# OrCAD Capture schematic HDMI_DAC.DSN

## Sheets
1 RGB: size A
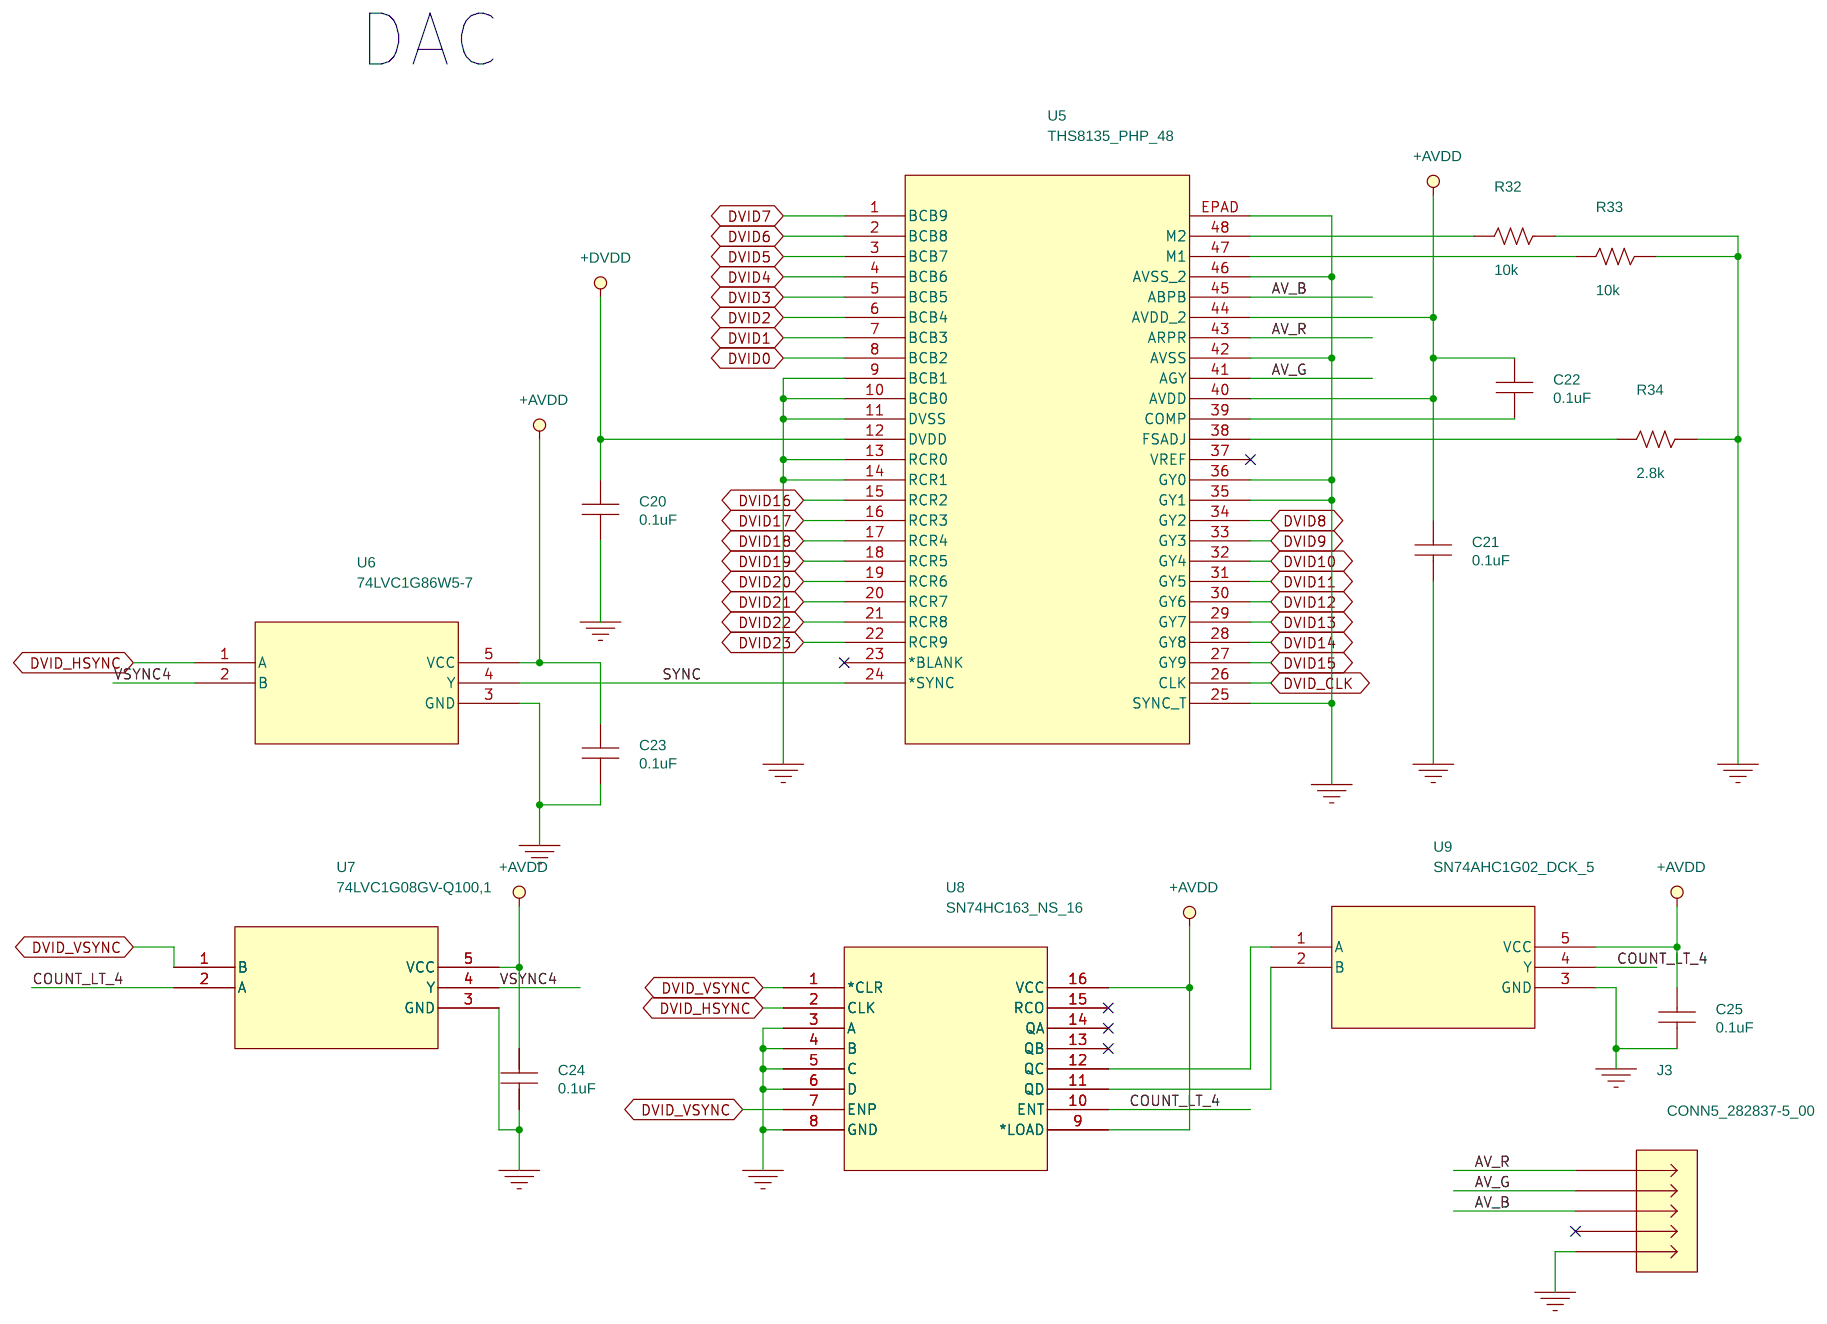
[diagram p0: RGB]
2 HDMI: size A
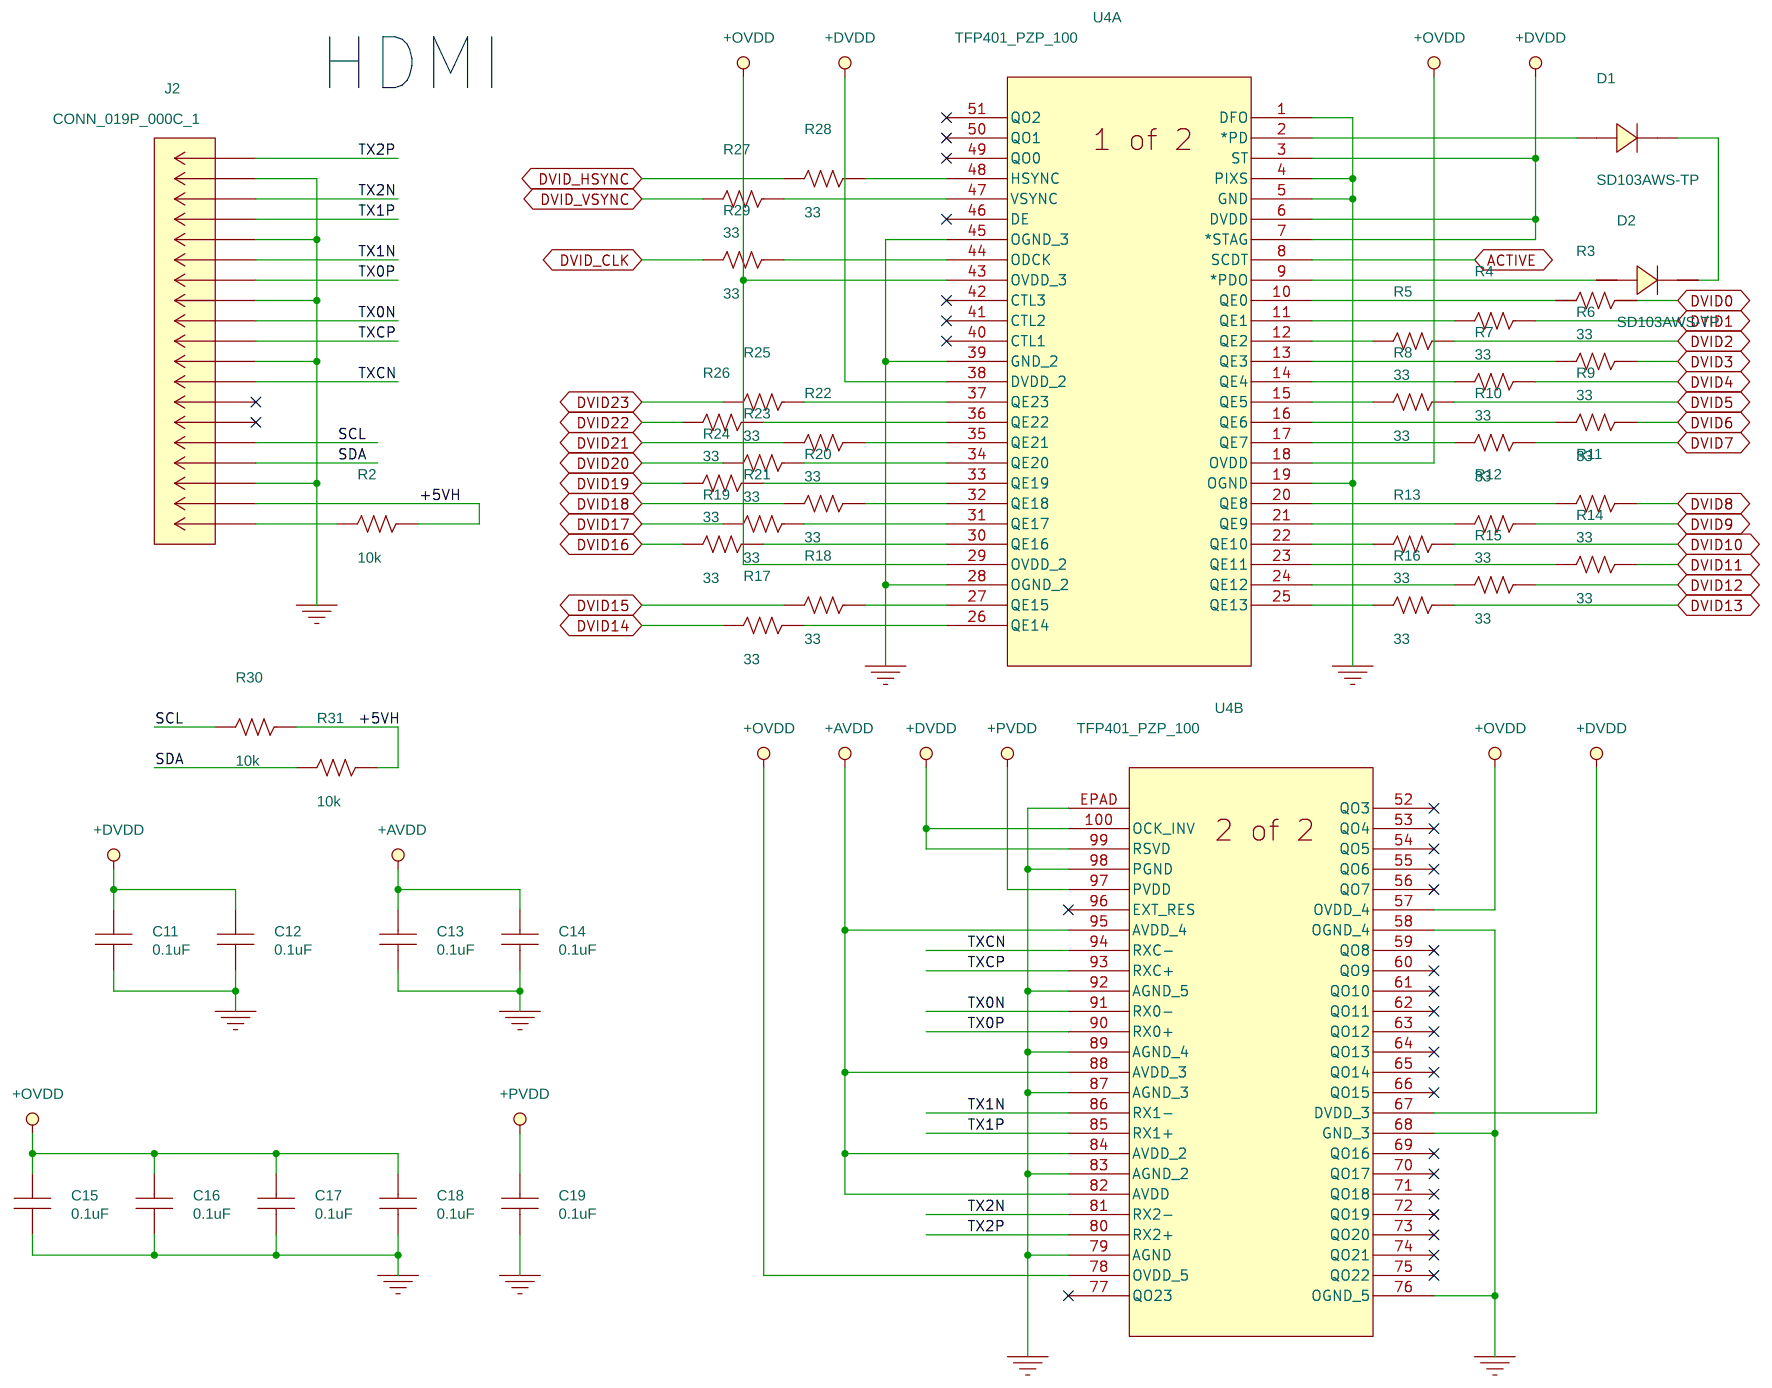
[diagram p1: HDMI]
3 POWER: size A
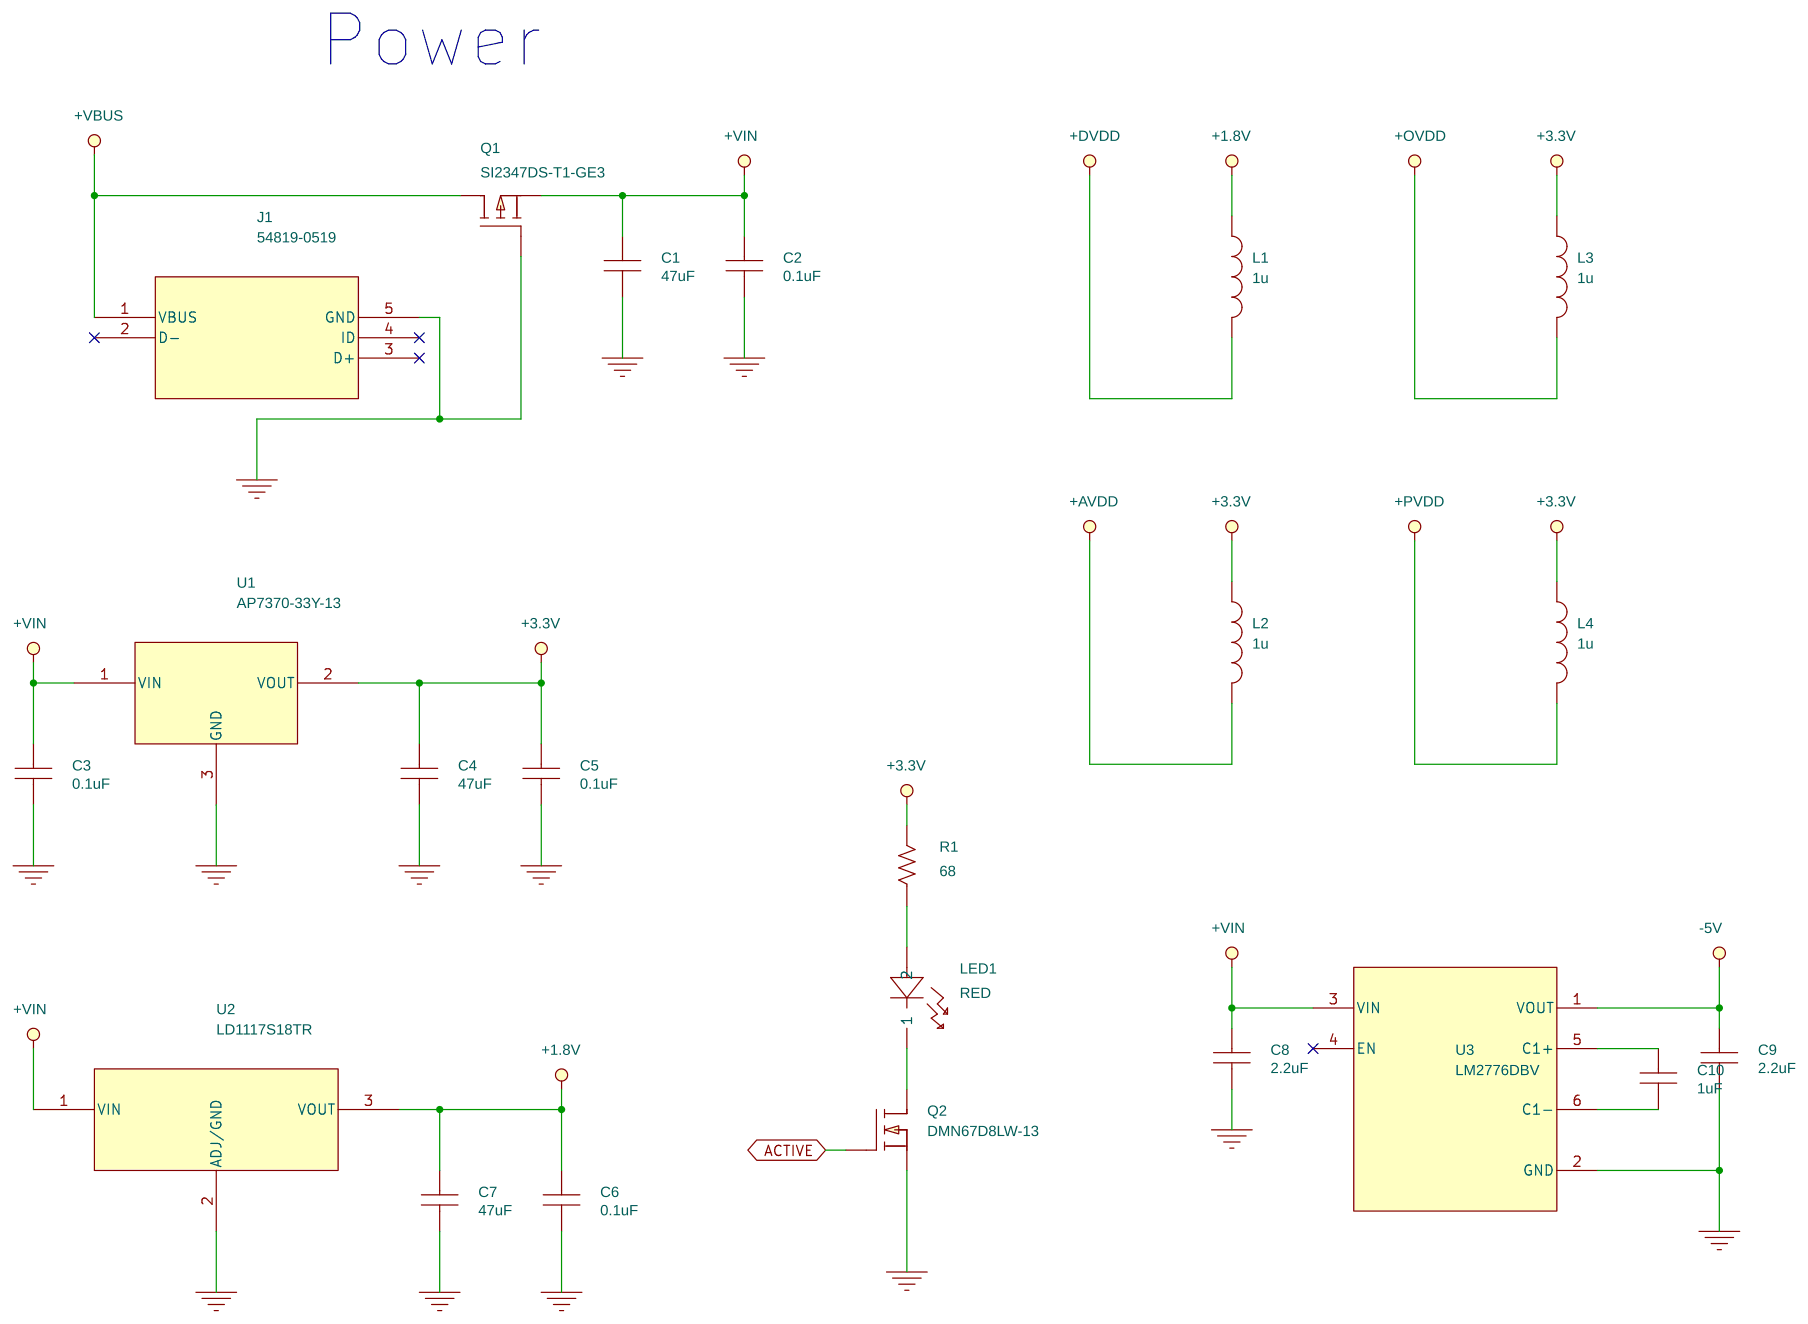
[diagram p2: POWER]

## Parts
sheet HDMI
C11  0.1uF  [SMC0603]
C12  0.1uF  [SMC0603]
C13  0.1uF  [SMC0603]
C14  0.1uF  [SMC0603]
C15  0.1uF  [SMC0603]
C16  0.1uF  [SMC0603]
C17  0.1uF  [SMC0603]
C18  0.1uF  [SMC0603]
C19  0.1uF  [SMC0603]
D1  SD103AWS-TP  [SMD0805]
D2  SD103AWS-TP  [SMD0805]
J2  CONN_019P_000C_1  [CONN_208658-1051_MOL]
R2  10k  [SMR0603]
R3  33  [SMR0603]
R4  33  [SMR0603]
R5  33  [SMR0603]
R6  33  [SMR0603]
R7  33  [SMR0603]
R8  33  [SMR0603]
R9  33  [SMR0603]
R10  33  [SMR0603]
R11  33  [SMR0603]
R12  33  [SMR0603]
R13  33  [SMR0603]
R14  33  [SMR0603]
R15  33  [SMR0603]
R16  33  [SMR0603]
R17  33  [SMR0603]
R18  33  [SMR0603]
R19  33  [SMR0603]
R20  33  [SMR0603]
R21  33  [SMR0603]
R22  33  [SMR0603]
R23  33  [SMR0603]
R24  33  [SMR0603]
R25  33  [SMR0603]
R26  33  [SMR0603]
R27  33  [SMR0603]
R28  33  [SMR0603]
R29  33  [SMR0603]
R30  10k  [SMR0603]
R31  10k  [SMR0603]
U4  TFP401_PZP_100  [PZP100_5P2X5P2]  (sections A,B)
sheet POWER
C1  47uF  [SMC1206]
C2  0.1uF  [SMC0603]
C3  0.1uF  [SMC0603]
C4  47uF  [SMC1206]
C5  0.1uF  [SMC0603]
C6  0.1uF  [SMC0603]
C7  47uF  [SMC1206]
C8  2.2uF  [SMC0603]
C9  2.2uF  [SMC0603]
C10  1uF  [SMC0603]
J1  54819-0519  [54819-0519_MOL]
L1  1u  [SMR0603]
L2  1u  [SMR0603]
L3  1u  [SMR0603]
L4  1u  [SMR0603]
LED1  RED  [LED_LTL-307E_LTO]
Q1  SI2347DS-T1-GE3  [SOT23]
Q2  DMN67D8LW-13  [SOT23]
R1  68  [SMR0603]
U1  AP7370-33Y-13  [SOT89]
U2  LD1117S18TR  [SOT89]
U3  LM2776DBV  [DBV0006A_N]
sheet RGB
C20  0.1uF  [SMC0603]
C21  0.1uF  [SMC0603]
C22  0.1uF  [SMC0603]
C23  0.1uF  [SMC0603]
C24  0.1uF  [SMC0603]
C25  0.1uF  [SMC0603]
J3  CONN5_282837-5_00  [CONN5_282837-5_TEC]
R32  10k  [SMR0603]
R33  10k  [SMR0603]
R34  2.8k  [SMR0603]
U5  THS8135_PHP_48  [PHP48_4P1X4P1]
U6  74LVC1G86W5-7  [SOT25_DIO]
U7  74LVC1G08GV-Q100,1  [SC-74A_SOT753_NEX]
U8  SN74HC163_NS_16  [NS16]
U9  SN74AHC1G02_DCK_5  [DCK5]

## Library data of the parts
C1-C25 = CAP_NP
D1 D2 = DIODE_0
J2 = 2086581051
R1-R34 = R
U4 = TFP401PZP
J1 = 548190519
L1-L4 = INDUCTOR
LED1 = LTL-307E_0
Q1 = MOSFET_EP_GSD
Q2 = MOSFET_EN_GSD
U1 = AP7370-33Y-13_2
U2 = LD1117S18TR_2
U3 = LM2776DBVT
J3 = 282837-5
U5 = THS8135PHP
U6 = 74LVC1G86W5-7
U7 = 74LVC1G08GV-Q100,1
U8 = SN74HC163NSR
U9 = SN74AHC1G02DCKRG4

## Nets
+1.8V: C6.1 C7.1 L1.1 U2.3(VOUT)
+3.3V: C4.1 C5.1 L2.1 L3.1 L4.1 R1.2 U1.2(VOUT)
+5VH: J2.18 R2.1 R30.1 R31.1
+AVDD: C13.1 C14.1 C21.1 C22.1 C23.1 C24.1 C25.1 L2.2 U4.82(AVDD) U4.84(AVDD_2) U4.88(AVDD_3) U4.95(AVDD_4) U5.40(AVDD) U5.44(AVDD_2) U6.5(VCC) U7.5(VCC) U8.9(*LOAD) U8.16(VCC) U9.5(VCC)
+DVDD: C11.1 C12.1 C20.1 L1.2 U4.3(ST) U4.6(DVDD) U4.7(*STAG) U4.38(DVDD_2) U4.67(DVDD_3) U4.99(RSVD) U4.100(OCK_INV) U5.12(DVDD)
+PVDD: C19.1 L4.2 U4.97(PVDD)
+VBUS: J1.1(VBUS) Q1.3(D)
+VIN: C1.1 C2.1 C3.1 C8.1 Q1.2(S) U1.1(VIN) U2.1(VIN) U3.3(VIN)
-5V: C9.1 U3.1(VOUT)
0: C1.2 C2.2 C3.2 C4.2 C5.2 C6.2 C7.2 C8.2 C9.2 C11.2 C12.2 C13.2 C14.2 C15.2 C16.2 C17.2 C18.2 C19.2 C20.2 C21.2 C23.2 C24.2 C25.2 J1.5(GND) J2.2 J2.5 J2.8 J2.11 J2.17 J3.5 Q1.1(G) Q2.2(S) R32.1 R33.1 R34.1 U1.3(GND) U2.2(ADJ/GND) U3.2(GND) U4.1(DFO) U4.4(PIXS) U4.5(GND) U4.19(OGND) U4.28(OGND_2) U4.39(GND_2) U4.45(OGND_3) U4.58(OGND_4) U4.68(GND_3) U4.76(OGND_5) U4.79(AGND) U4.83(AGND_2) U4.87(AGND_3) U4.89(AGND_4) U4.92(AGND_5) U4.98(PGND) U4.EPAD U5.9(BCB1) U5.10(BCB0) U5.11(DVSS) U5.13(RCR0) U5.14(RCR1) U5.25(SYNC_T) U5.35(GY1) U5.36(GY0) U5.42(AVSS) U5.46(AVSS_2) U5.EPAD U6.3(GND) U7.3(GND) U8.3(A) U8.4(B) U8.5(C) U8.6(D) U8.8(GND) U9.3(GND)
+OVDD: C15.1 C16.1 C17.1 C18.1 L3.2 U4.18(OVDD) U4.29(OVDD_2) U4.43(OVDD_3) U4.57(OVDD_4) U4.78(OVDD_5)
ACTIVE: Q2.1(G) U4.8(SCDT)
AV_B: J3.3 U5.45(ABPB)
AV_G: J3.2 U5.41(AGY)
AV_R: J3.1 U5.43(ARPR)
COUNT_LT_4: U7.2(A) U8.10(ENT) U9.4(Y)
DVID0: R3.1 U5.8(BCB2)
DVID1: R4.1 U5.7(BCB3)
DVID2: R5.1 U5.6(BCB4)
DVID3: R6.1 U5.5(BCB5)
DVID4: R7.1 U5.4(BCB6)
DVID5: R8.1 U5.3(BCB7)
DVID6: R9.1 U5.2(BCB8)
DVID7: R10.1 U5.1(BCB9)
DVID8: R11.1 U5.34(GY2)
DVID9: R12.1 U5.33(GY3)
DVID10: R13.1 U5.32(GY4)
DVID11: R14.1 U5.31(GY5)
DVID12: R15.1 U5.30(GY6)
DVID13: R16.1 U5.29(GY7)
DVID14: R17.2 U5.28(GY8)
DVID15: R18.2 U5.27(GY9)
DVID16: R19.2 U5.15(RCR2)
DVID17: R21.2 U5.16(RCR3)
DVID18: R20.2 U5.17(RCR4)
DVID19: R24.2 U5.18(RCR5)
DVID20: R23.2 U5.19(RCR6)
DVID21: R22.2 U5.20(RCR7)
DVID22: R26.2 U5.21(RCR8)
DVID23: R25.2 U5.22(RCR9)
DVID_CLK: R29.2 U5.26(CLK)
DVID_HSYNC: R28.2 U6.1(A) U8.2(CLK)
DVID_VSYNC: R27.2 U7.1(B) U8.1(*CLR) U8.7(ENP)
SCL: J2.15 R30.2
SDA: J2.16 R31.2
SYNC: U5.24(*SYNC) U6.4(Y)
TX0N: J2.9 U4.91(RX0-)
TX0P: J2.7 U4.90(RX0+)
TX1N: J2.6 U4.86(RX1-)
TX1P: J2.4 U4.85(RX1+)
TX2N: J2.3 U4.81(RX2-)
TX2P: J2.1 U4.80(RX2+)
TXCN: J2.12 U4.94(RXC-)
TXCP: J2.10 U4.93(RXC+)
VSYNC4: U6.2(B) U7.4(Y)
N03253: C10.1 U3.5(C1+)
N03257: C10.2 U3.6(C1-)
N03589: LED1.2(1) Q2.3(D)
N03620: LED1.1(2) R1.1
N04135: J2.19 R2.2
N11616: R3.2 U4.10(QE0)
N11680: R4.2 U4.11(QE1)
N11691: R5.2 U4.12(QE2)
N11721: R6.2 U4.13(QE3)
N11753: R7.2 U4.14(QE4)
N11785: R8.2 U4.15(QE5)
N11817: R9.2 U4.16(QE6)
N11849: R10.2 U4.17(QE7)
N12249: R11.2 U4.20(QE8)
N12281: R12.2 U4.21(QE9)
N12313: R13.2 U4.22(QE10)
N12345: R14.2 U4.23(QE11)
N12377: R15.2 U4.24(QE12)
N12409: R16.2 U4.25(QE13)
N12613: R17.1 U4.26(QE14)
N13128: R18.1 U4.27(QE15)
N13531: R19.1 U4.30(QE16)
N13809: R20.1 U4.32(QE18)
N13817: R21.1 U4.31(QE17)
N13972: R22.1 U4.35(QE21)
N14004: R23.1 U4.34(QE20)
N14012: R24.1 U4.33(QE19)
N14149: R25.1 U4.37(QE23)
N14157: R26.1 U4.36(QE22)
N14872: R27.1 U4.47(VSYNC)
N15122: R28.1 U4.48(HSYNC)
N15187: R29.1 U4.44(ODCK)
N15634: D1.A U4.2(*PD)
N15666: D2.A U4.9(*PDO)
N15670: D1.C(K) D2.C(K)
N21441: R32.2 U5.48(M2)
N21445: R33.2 U5.47(M1)
N21637: C22.2 U5.39(COMP)
N21681: R34.2 U5.38(FSADJ)
N25706: U8.11(QD) U9.2(B)
N25713: U8.12(QC) U9.1(A)

Not connected (* = marked no-connect by the designer): J1 2(D-)* 3(D+)* 4(ID)*; J2 13* 14*; J3 4*; U3 4(EN)*; U4 40(CTL1)* 41(CTL2)* 42(CTL3)* 46(DE)* 49(QO0)* 50(QO1)* 51(QO2)* 52(QO3)* 53(QO4)* 54(QO5)* 55(QO6)* 56(QO7)* 59(QO8)* 60(QO9)* 61(QO10)* 62(QO11)* 63(QO12)* 64(QO13)* 65(QO14)* 66(QO15)* 69(QO16)* 70(QO17)* 71(QO18)* 72(QO19)* 73(QO20)* 74(QO21)* 75(QO22)* 77(QO23)* 96(EXT_RES)*; U5 23(*BLANK)* 37(VREF)*; U8 13(QB)* 14(QA)* 15(RCO)*

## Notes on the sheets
sheet 1
- DAC
sheet 2
- HDMI
sheet 3
- Power
